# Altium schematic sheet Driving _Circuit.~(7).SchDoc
size A4; SheetNumber: 1; SheetTotal: 1; SPICEModelCacheBUJQYFZZ: <root> / <DocumentId>BUJQYFZZ</DocumentId> / </root>
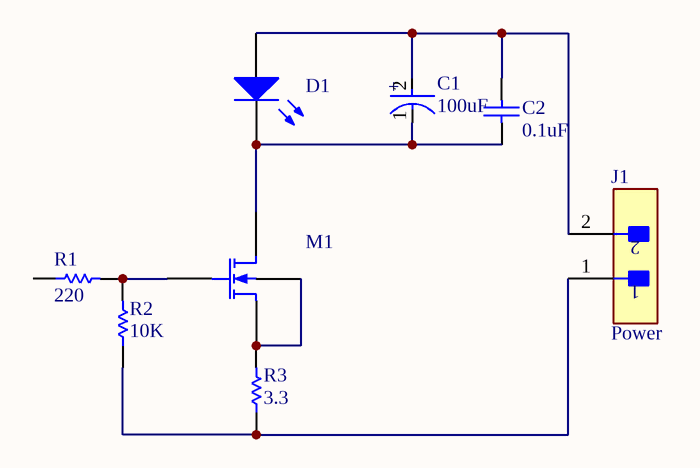
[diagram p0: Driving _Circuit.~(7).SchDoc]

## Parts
C1  100uF  [FP-RAD-TH-D_6_3_0_5-L_11-MFG]
C2  value 0.1uF  (hidden comment: Capacitor)
D1  Light-Emitting Diode  (value not drawn)
J1  Power  [FP-TMM-102-03-T-S-MFG]
M1  N-channel MOS1 MOSFET Shichman and Hodges Model  (value not drawn)
R1  value 220  (hidden comment: Resistor)
R2  value 10K  (hidden comment: Resistor)
R3  value 3.3  (hidden comment: Resistor)

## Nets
NetC1_1: C1.1(C) C2.1 D1.2(K) M1.1(D)
NetC1_2: C1.2(A) C2.2 D1.1(A) J1.2
NetJ1_1: J1.1 R2.1 R3.1
NetM1_2: M1.2(G) R1.2 R2.2
NetM1_3: M1.3(S) M1.4(B) R3.2

Not connected (* = marked no-connect by the designer): R1 1

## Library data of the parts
C1 = CMP-05427-000856-1: Aluminum Electrolytic Capacitors (Radial Lead Type) 100uF ±20% 25V; Lead Diameter: 0.5mm; Polarity: Polar; Ripple Current: 455mA; Impedance: 130mR; Life (Hours): 2000Hour
C2 = Capacitor: SimulationGenericComponent: True
D1 = LED: LITEON IR LED; AF: 1; BV: 0; BV_MAX: 1e99; EG: 1.11; FC: 0.5; IBV: 0.001; IS: 1e-14; MJSW: 0.33; NTUN: 30; TNOM: 27; XTI: 3; SimulationGenericComponent: True
J1 = CMP-02766-001621-1: CONN HEADER VERT 2POS 2MM; Max Voltage Rating (AC): 500V; Gender: Male; Number of Positions: 2; Max Current Rating: 3.9A
M1 = MOSFET N-ch Lev1: IRLZ44N NMOS; CBD: 0; FC: 0.5; IS: 1e-14; KP: 2e-05; PB: 0.8; PHI: 0.6; TNOM: 27; SimulationGenericComponent: True
R1-R3 = Resistor: TC1: 0; SimulationGenericComponent: True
